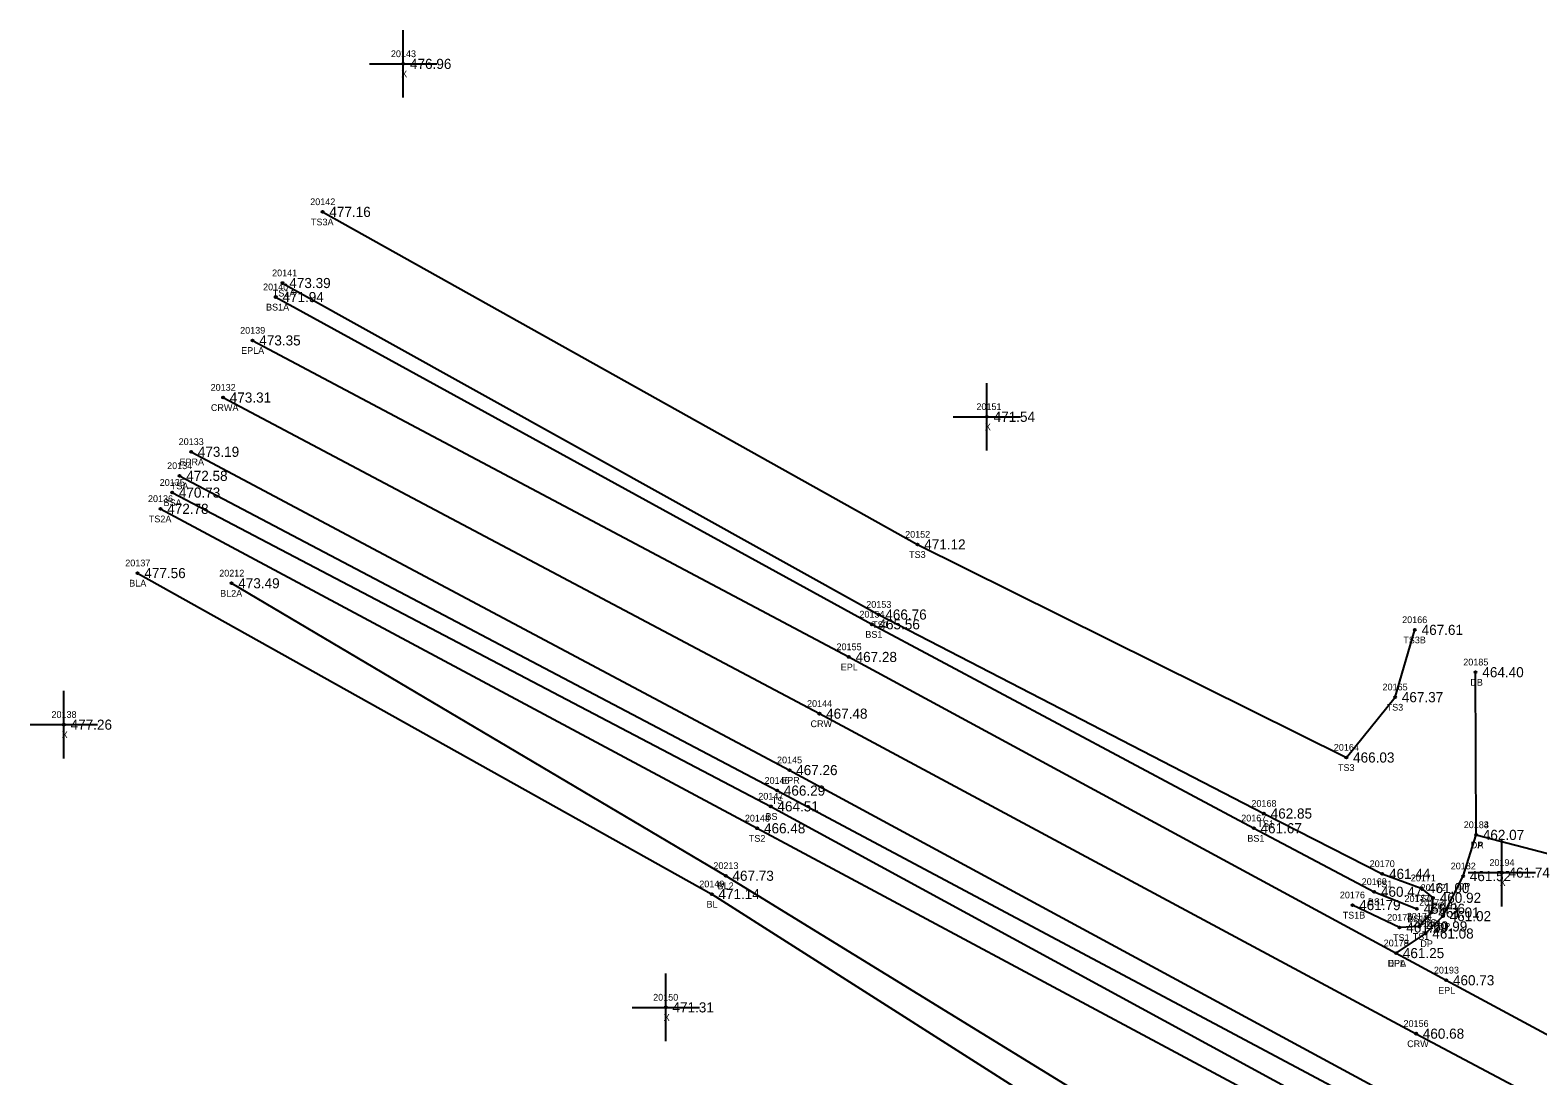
# Model space of a CAD drawing. Extents: x 1810114 to 1811498, y 790790 to 791824.
# Drawn here: x 1810114.3 to 1810337.9, y 791524.2 to 791679.3 of the extents above; entities that cross this region are included whole.
import ezdxf

# ---------------------------------------------------------------- set-up
doc = ezdxf.new("R2010")
doc.units = 0
for name, color, linetype in [('RD_DTM_BkLn1', 7, 'Continuous'), ('RD_DTM_BkLn2', 7, 'Continuous'), ('RD_DTM_BkLn_txCode', 7, 'Continuous'), ('RD_EX_Driveway', 7, 'Continuous'), ('RD_EX_Driveway_txCode', 7, 'Continuous'), ('RD_EX_Misc', 7, 'Continuous'), ('RD_EX_Misc_txCode', 7, 'Continuous'), ('RD_EX_Road', 7, 'Continuous'), ('RD_EX_Road_txCode', 7, 'Continuous'), ('RD_EX_TX_Driveway_ELEV', 7, 'Continuous'), ('RD_EX_TX_Misc_ELEV', 7, 'Continuous'), ('RD_EX_TX_Road_ELEV', 7, 'Continuous'), ('RD_HC_Survey_ELEV', 7, 'Continuous'), ('RD_HC_Survey_txCode', 7, 'Continuous'), ('RD_SMD_Locator', 7, 'Continuous')]:
    doc.layers.add(name, color=color, linetype=linetype)

msp = doc.modelspace()

# ---------------------------------------------------------------- linework, layer by layer
at = {"layer": 'RD_DTM_BkLn1'}
for points in [[(1810142.92, 791624.85), (1810231.36, 791577.96), (1810319.85, 791530.5), (1810408.61, 791483.38), (1810496.8, 791436.85), (1810585.08, 791388.93), (1810674.47, 791342.37), (1810763.64, 791295.68)], [(1810130.25, 791598.81), (1810215.39, 791551.2), (1810300.2, 791497.21), (1810392.2, 791452.25), (1810484.95, 791413.19)], [(1810144.18, 791597.3), (1810217.47, 791553.92), (1810302.26, 791501.79), (1810394.73, 791457), (1810484.95, 791413.19)]]:
    msp.add_lwpolyline(points, dxfattribs=at)
at = {"layer": 'RD_DTM_BkLn2'}
for points in [[(1810157.69, 791652.38), (1810245.91, 791603.06), (1810309.51, 791571.46), (1810316.74, 791580.41), (1810319.68, 791590.39)], [(1810150.73, 791639.75), (1810239.13, 791591.21), (1810295.78, 791560.97), (1810313.64, 791551.55), (1810319.97, 791549.03)], [(1810151.75, 791641.83), (1810240.14, 791592.66), (1810297.29, 791563.15), (1810314.84, 791554.2), (1810320.62, 791552.1), (1810322.36, 791550.65), (1810322.14, 791548.47), (1810320.31, 791546.41), (1810317.4, 791546.25), (1810310.41, 791549.57)], [(1810136.46, 791613.23), (1810225.09, 791566.55), (1810313.34, 791519.56), (1810402.58, 791471.61), (1810490.03, 791423.34), (1810516.06, 791407.46), (1810541.24, 791393.02), (1810575.56, 791368.65), (1810662.82, 791320.73), (1810730.85, 791285.33), (1810742.82, 791282.19), (1810752.34, 791280.87), (1810757.12, 791283.77)], [(1810135.37, 791610.75), (1810224.14, 791564.21), (1810311.68, 791516.56), (1810401.2, 791468.88), (1810488.81, 791421.27), (1810514.98, 791405.31), (1810539.89, 791390.39), (1810572.74, 791363.8), (1810659.47, 791316.31), (1810726.51, 791276.73), (1810738.6, 791270.6), (1810748.52, 791266.73), (1810763.99, 791268.4)], [(1810133.65, 791608.34), (1810222.15, 791560.96), (1810310.01, 791513.91), (1810399.26, 791465.14), (1810487.96, 791419.17), (1810513.17, 791403.16), (1810538.21, 791387.66)]]:
    msp.add_lwpolyline(points, dxfattribs=at)
at = {"layer": 'RD_EX_Driveway'}
msp.add_line((1810328.75, 791559.98), (1810328.68, 791584.11), dxfattribs=at)
msp.add_lwpolyline([(1810316.89, 791542.45), (1810321.26, 791545.35), (1810323.84, 791547.93), (1810326.82, 791553.87), (1810328.75, 791559.98), (1810340.54, 791556.94), (1810340.76, 791548.25), (1810342.19, 791540.05), (1810344.08, 791532.67), (1810347.02, 791528.25), (1810350.04, 791524.6)], dxfattribs=at)
at = {"layer": 'RD_EX_Misc'}
for p, q in [((1810169.65, 791669.33), (1810169.65, 791679.33)), ((1810164.65, 791674.33), (1810174.65, 791674.33)), ((1810256.21, 791616.99), (1810256.21, 791626.99)), ((1810251.21, 791621.99), (1810261.21, 791621.99)), ((1810119.32, 791571.33), (1810119.32, 791581.33)), ((1810114.32, 791576.33), (1810124.32, 791576.33)), ((1810332.56, 791549.38), (1810332.56, 791559.38)), ((1810327.56, 791554.38), (1810337.56, 791554.38)), ((1810208.58, 791529.4), (1810208.58, 791539.4)), ((1810203.58, 791534.4), (1810213.58, 791534.4))]:
    msp.add_line(p, q, dxfattribs=at)
at = {"layer": 'RD_EX_Road'}
for points in [[(1810147.3, 791633.32), (1810235.73, 791586.37), (1810316.89, 791542.45), (1810324.32, 791538.42), (1810350.04, 791524.6), (1810412.94, 791490.75), (1810461.45, 791466.07), (1810501.18, 791444.55), (1810589.18, 791397.37), (1810679.08, 791351.18), (1810768.4, 791304.34)], [(1810138.18, 791616.8), (1810226.92, 791569.59), (1810315.11, 791521.87), (1810404.37, 791475.11), (1810492.73, 791428.56), (1810580.86, 791380.55), (1810670.21, 791334.43), (1810759.54, 791287.61)]]:
    msp.add_lwpolyline(points, dxfattribs=at)
at = {"layer": 'RD_SMD_Locator'}
for centre in [(1810169.65, 791674.33), (1810157.69, 791652.38), (1810151.75, 791641.83), (1810150.73, 791639.75), (1810147.3, 791633.32), (1810142.92, 791624.85), (1810256.21, 791621.99), (1810138.18, 791616.8), (1810136.46, 791613.23), (1810135.37, 791610.75), (1810133.65, 791608.34), (1810245.91, 791603.06), (1810130.25, 791598.81), (1810144.18, 791597.3), (1810240.14, 791592.66), (1810239.13, 791591.21), (1810319.68, 791590.39), (1810235.73, 791586.37), (1810328.68, 791584.11), (1810316.74, 791580.41), (1810231.36, 791577.96), (1810119.32, 791576.33), (1810309.51, 791571.46), (1810226.92, 791569.59), (1810225.09, 791566.55), (1810224.14, 791564.21), (1810297.29, 791563.15), (1810222.15, 791560.96), (1810295.78, 791560.97), (1810328.75, 791559.98), (1810328.75, 791559.98), (1810217.47, 791553.92), (1810314.84, 791554.2), (1810326.82, 791553.87), (1810332.56, 791554.38), (1810215.39, 791551.2), (1810313.64, 791551.55), (1810320.62, 791552.1), (1810322.36, 791550.65), (1810310.41, 791549.57), (1810319.97, 791549.03), (1810322.14, 791548.47), (1810323.84, 791547.93), (1810317.4, 791546.25), (1810320.31, 791546.41), (1810321.26, 791545.35), (1810316.89, 791542.45), (1810316.89, 791542.45), (1810324.32, 791538.42), (1810208.58, 791534.4), (1810319.85, 791530.5)]:
    msp.add_circle(centre, 0.15, dxfattribs=at)

# ---------------------------------------------------------------- texts
at = {"layer": 'RD_DTM_BkLn_txCode'}
for s, p in [('20142', (1810155.85, 791653.38)), ('TS3A', (1810155.96, 791650.38)), ('20141', (1810150.2, 791642.83)), ('20140', (1810148.86, 791640.75)), ('TS1A', (1810150.3, 791639.83)), ('BS1A', (1810149.3, 791637.75)), ('20134', (1810134.63, 791614.23)), ('20135', (1810133.53, 791611.75)), ('TSA', (1810135.18, 791611.23)), ('20136', (1810131.79, 791609.34)), ('BSA', (1810134.1, 791608.75)), ('TS2A', (1810131.92, 791606.34)), ('20152', (1810244.08, 791604.06)), ('TS3', (1810244.67, 791601.06)), ('20137', (1810128.42, 791599.81)), ('BLA', (1810129.01, 791596.81)), ('20212', (1810142.35, 791598.3)), ('BL2A', (1810142.49, 791595.3)), ('20154', (1810237.3, 791592.21)), ('20153', (1810238.31, 791593.66)), ('TS1', (1810239.18, 791590.66)), ('20166', (1810317.79, 791591.39)), ('BS1', (1810238.18, 791589.21)), ('TS3B', (1810317.96, 791588.39)), ('20165', (1810314.88, 791581.41)), ('TS3', (1810315.49, 791578.41)), ('20164', (1810307.65, 791572.46)), ('TS3', (1810308.27, 791569.46)), ('20146', (1810223.23, 791567.55)), ('20147', (1810222.3, 791565.21)), ('TS', (1810224.29, 791564.55)), ('20168', (1810295.43, 791564.15)), ('20148', (1810220.31, 791561.96)), ('BS', (1810223.36, 791562.21)), ('20167', (1810293.92, 791561.97)), ('TS1', (1810296.33, 791561.15)), ('TS2', (1810220.9, 791558.96)), ('BS1', (1810294.83, 791558.97)), ('20213', (1810215.64, 791554.92)), ('20170', (1810312.97, 791555.2)), ('20149', (1810213.55, 791552.2)), ('BL2', (1810216.27, 791551.92)), ('20169', (1810311.79, 791552.55)), ('TS1', (1810313.88, 791552.2)), ('20171', (1810319.07, 791553.1)), ('20172', (1810320.53, 791551.65)), ('BL', (1810214.63, 791549.2)), ('20176', (1810308.55, 791550.57)), ('BS1', (1810312.7, 791549.55)), ('20177', (1810318.14, 791550.03)), ('TS1', (1810319.66, 791550.1)), ('20173', (1810320.31, 791549.47)), ('TS1B', (1810308.97, 791547.57)), ('20175', (1810315.57, 791547.25)), ('20174', (1810318.47, 791547.41)), ('BS1B', (1810318.55, 791547.03)), ('TS1', (1810321.4, 791548.65)), ('TS1', (1810321.18, 791546.47)), ('TS1', (1810316.44, 791544.25)), ('TS1', (1810319.35, 791544.41))]:
    msp.add_text(s, height=1, dxfattribs=at).set_placement(p)
at = {"layer": 'RD_EX_Driveway_txCode'}
for s, p in [('20185', (1810326.85, 791585.11)), ('DB', (1810327.9, 791582.11)), ('20183', (1810326.92, 791560.98)), ('20184', (1810326.92, 791560.98)), ('DA', (1810327.96, 791557.98)), ('DP', (1810327.97, 791557.98)), ('20182', (1810324.99, 791554.87)), ('DP', (1810326.04, 791551.87)), ('20181', (1810322.29, 791548.93)), ('20180', (1810319.39, 791546.35)), ('DP', (1810323.06, 791545.93)), ('20179', (1810315.05, 791543.45)), ('DP', (1810320.48, 791543.35)), ('DPA', (1810315.62, 791540.45))]:
    msp.add_text(s, height=1, dxfattribs=at).set_placement(p)
at = {"layer": 'RD_EX_Misc_txCode'}
for s, p in [('20143', (1810167.82, 791675.33)), ('X', (1810169.34, 791672.33)), ('20151', (1810254.65, 791622.99)), ('X', (1810255.89, 791619.99)), ('20138', (1810117.48, 791577.33)), ('X', (1810119, 791574.33)), ('20194', (1810330.73, 791555.38)), ('X', (1810332.25, 791552.38)), ('20150', (1810206.71, 791535.4)), ('X', (1810208.27, 791532.4))]:
    msp.add_text(s, height=1, dxfattribs=at).set_placement(p)
at = {"layer": 'RD_EX_Road_txCode'}
for s, p in [('20139', (1810145.46, 791634.32)), ('EPLA', (1810145.6, 791631.32)), ('20133', (1810136.34, 791617.8)), ('EPRA', (1810136.46, 791614.8)), ('20155', (1810233.9, 791587.37)), ('EPL', (1810234.53, 791584.37)), ('20145', (1810225.08, 791570.59)), ('EPR', (1810225.69, 791567.59)), ('20178', (1810315.05, 791543.45)), ('EPL', (1810315.68, 791540.45)), ('20193', (1810322.49, 791539.42)), ('EPL', (1810323.12, 791536.42))]:
    msp.add_text(s, height=1, dxfattribs=at).set_placement(p)
at = {"layer": 'RD_EX_TX_Driveway_ELEV'}
for s, p in [('464.40', (1810329.68, 791583.36)), ('462.07', (1810329.75, 791559.23)), ('462.07', (1810329.75, 791559.23)), ('461.52', (1810327.82, 791553.12)), ('461.02', (1810324.84, 791547.18)), ('461.08', (1810322.26, 791544.6)), ('461.25', (1810317.89, 791541.7))]:
    msp.add_text(s, height=1.5, dxfattribs=at).set_placement(p)
at = {"layer": 'RD_EX_TX_Misc_ELEV'}
for s, p in [('476.96', (1810170.65, 791673.58)), ('477.16', (1810158.69, 791651.63)), ('473.39', (1810152.75, 791641.08)), ('471.94', (1810151.73, 791639)), ('471.54', (1810257.21, 791621.24)), ('472.58', (1810137.46, 791612.48)), ('470.73', (1810136.37, 791610)), ('472.78', (1810134.65, 791607.59)), ('471.12', (1810246.91, 791602.31)), ('477.56', (1810131.25, 791598.06)), ('473.49', (1810145.18, 791596.55)), ('466.76', (1810241.14, 791591.91)), ('465.56', (1810240.13, 791590.46)), ('467.61', (1810320.68, 791589.64)), ('467.37', (1810317.74, 791579.66)), ('477.26', (1810120.32, 791575.58)), ('466.03', (1810310.51, 791570.71)), ('466.29', (1810226.09, 791565.8)), ('464.51', (1810225.14, 791563.46)), ('462.85', (1810298.29, 791562.4)), ('466.48', (1810223.15, 791560.21)), ('461.67', (1810296.78, 791560.22)), ('467.73', (1810218.47, 791553.17)), ('461.44', (1810315.84, 791553.45)), ('461.74', (1810333.56, 791553.63)), ('461.00', (1810321.62, 791551.35)), ('471.14', (1810216.39, 791550.45)), ('461.79', (1810311.41, 791548.82)), ('460.47', (1810314.64, 791550.8)), ('460.92', (1810323.36, 791549.9)), ('459.36', (1810320.97, 791548.28)), ('461.01', (1810323.14, 791547.72)), ('461.29', (1810318.4, 791545.5)), ('460.99', (1810321.31, 791545.66)), ('471.31', (1810209.58, 791533.65))]:
    msp.add_text(s, height=1.5, dxfattribs=at).set_placement(p)
at = {"layer": 'RD_EX_TX_Road_ELEV'}
for s, p in [('473.35', (1810148.3, 791632.57)), ('473.19', (1810139.18, 791616.05)), ('467.28', (1810236.73, 791585.62)), ('467.26', (1810227.92, 791568.84)), ('461.25', (1810317.89, 791541.7)), ('460.73', (1810325.32, 791537.67))]:
    msp.add_text(s, height=1.5, dxfattribs=at).set_placement(p)
at = {"layer": 'RD_HC_Survey_ELEV'}
for s, p in [('473.31', (1810143.92, 791624.1)), ('467.48', (1810232.36, 791577.21)), ('460.68', (1810320.85, 791529.75))]:
    msp.add_text(s, height=1.5, dxfattribs=at).set_placement(p)
at = {"layer": 'RD_HC_Survey_txCode'}
for s, p in [('20132', (1810141.08, 791625.85)), ('CRWA', (1810141.12, 791622.85)), ('20144', (1810229.53, 791578.96)), ('CRW', (1810230.05, 791575.96)), ('20156', (1810317.99, 791531.5)), ('CRW', (1810318.53, 791528.5))]:
    msp.add_text(s, height=1, dxfattribs=at).set_placement(p)

doc.saveas('drawing.dxf')
